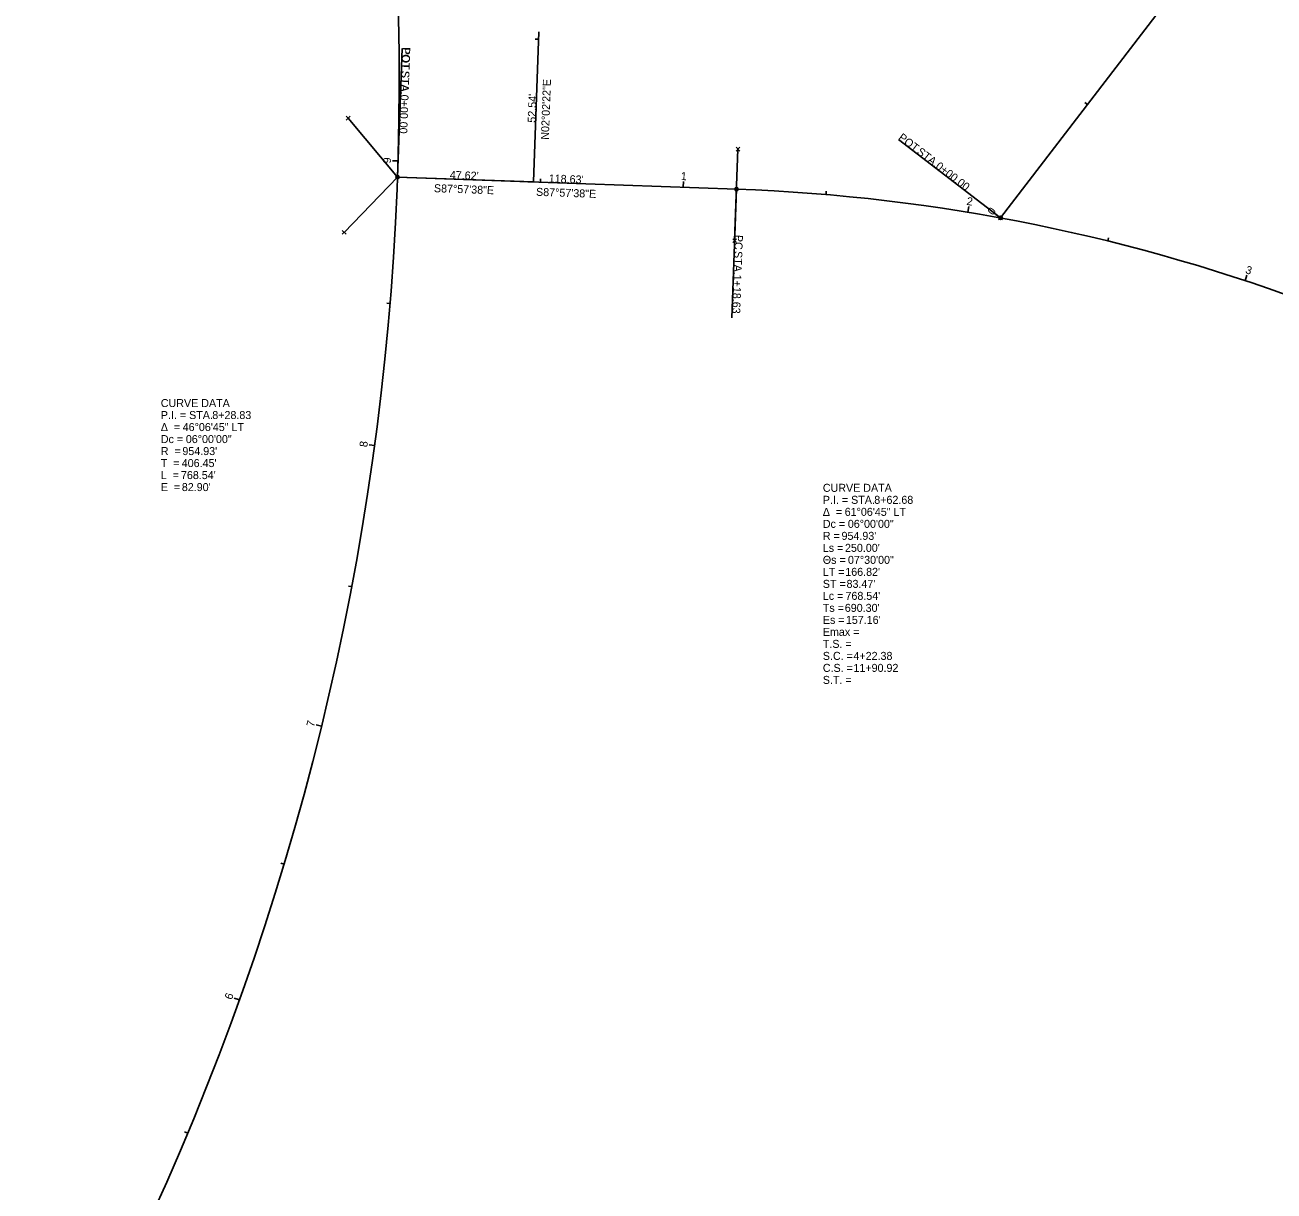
# Model space of a CAD drawing. Extents: x 1609531 to 1610891, y 471231 to 473177.
# Drawn here: x 1609986.3 to 1610423.2, y 471882.7 to 472290.7 of the extents above; entities that cross this region are included whole.
import ezdxf

# ---------------------------------------------------------------- set-up
doc = ezdxf.new("R2010")
doc.units = 0
for name, color, linetype in [('BR_X_SV_Shot_Marker', 7, 'Continuous'), ('Default', 7, 'Continuous'), ('DR_X_Ditch', 7, 'Continuous'), ('PM_X_Stop_Line', 7, 'Continuous'), ('PV_X_COP', 7, 'Continuous'), ('PV_X_Driveway', 7, 'Continuous'), ('PV_X_EOP', 7, 'Continuous'), ('PV_X_Shoulder_Aggregate', 7, 'Continuous'), ('RD_X_Cells', 7, 'Continuous'), ('RD_X_GR_Lt', 7, 'Continuous'), ('RD_X_GR_Rt', 7, 'Continuous'), ('SV_P_Mon_Cells_Set', 7, 'Continuous'), ('SV_X_Control_Cells_Found', 7, 'Continuous'), ('UT_X_Misc_Cells', 7, 'Continuous'), ('UT_X_Telecom_Cells', 7, 'Continuous')]:
    doc.layers.add(name, color=color, linetype=linetype)

msp = doc.modelspace()

# ---------------------------------------------------------------- linework, layer by layer
at = {"layer": 'Default'}
msp.add_line((1610116.63, 472237.49), (1610235.18, 472233.27), dxfattribs=at)
for centre, radius, start, end in [((1609162.3, 472271.47), 954.93, 329.64417, 15.75667), ((1610212.53, 471597.05), 636.62, 50.22722, 87.96056)]:
    msp.add_arc(centre, radius, start, end, dxfattribs=at)
at = {"layer": 'DR_X_Ditch'}
for p, q in [((1610166, 472285.76), (1610164.8, 472285.8)), ((1610164.22, 472235.79), (1610162.23, 472235.86))]:
    msp.add_line(p, q, dxfattribs=at)
at = {"layer": 'PM_X_Stop_Line'}
msp.add_line((1610116.63, 472237.49), (1610118.23, 472282.46), dxfattribs=at)
msp.add_circle((1610116.63, 472237.49), 0.6, dxfattribs=at)
at = {"layer": 'PV_X_COP'}
for p, q in [((1610098.69, 472257.45), (1610100.02, 472258.78)), ((1610098.69, 472258.78), (1610100.02, 472257.45)), ((1610235.02, 472246.59), (1610236.35, 472247.92)), ((1610235.02, 472247.92), (1610236.35, 472246.59)), ((1610326.85, 472222.53), (1610328.18, 472223.87)), ((1610326.85, 472223.87), (1610328.18, 472222.53)), ((1610097.26, 472217.47), (1610098.6, 472218.81)), ((1610097.26, 472218.81), (1610098.6, 472217.47)), ((1610233.88, 472214.61), (1610235.21, 472215.94)), ((1610233.88, 472215.94), (1610235.21, 472214.61))]:
    msp.add_line(p, q, dxfattribs=at)
at = {"layer": 'PV_X_Shoulder_Aggregate'}
for p, q in [((1610357.95, 472262.87), (1610356.99, 472263.6)), ((1610116.82, 472243.16), (1610114.82, 472243.22)), ((1610166.6, 472235.71), (1610166.64, 472236.91)), ((1610216.57, 472233.93), (1610216.64, 472235.93)), ((1610266.49, 472231.38), (1610266.6, 472232.57)), ((1610316.1, 472225.19), (1610316.42, 472227.16)), ((1610327.51, 472223.2), (1610325.93, 472224.42)), ((1610365.06, 472215.13), (1610365.35, 472216.29)), ((1610413.08, 472201.25), (1610413.71, 472203.15)), ((1610114.03, 472193.25), (1610112.83, 472193.35)), ((1610108.63, 472143.55), (1610106.65, 472143.81)), ((1610100.64, 472094.19), (1610099.46, 472094.42)), ((1610090.07, 472045.33), (1610088.13, 472045.8)), ((1610076.96, 471997.08), (1610075.82, 471997.43)), ((1610061.35, 471949.59), (1610059.47, 471950.26)), ((1610043.27, 471902.98), (1610042.17, 471903.44))]:
    msp.add_line(p, q, dxfattribs=at)
at = {"layer": 'RD_X_Cells'}
for p, q in [((1610116.63, 472237.49), (1610099.35, 472258.11)), ((1610234.54, 472215.28), (1610235.68, 472247.26)), ((1610097.93, 472218.14), (1610116.63, 472237.49))]:
    msp.add_line(p, q, dxfattribs=at)
at = {"layer": 'RD_X_GR_Rt'}
for p, q in [((1610164.22, 472235.79), (1610166.09, 472288.3)), ((1610116.63, 472237.49), (1610164.22, 472235.79))]:
    msp.add_line(p, q, dxfattribs=at)
at = {"layer": 'SV_P_Mon_Cells_Set'}
msp.add_circle((1610140.43, 472236.64), 0.05, dxfattribs=at)
msp.add_circle((1610140.43, 472236.64), 0.05, dxfattribs=at)
at = {"layer": 'SV_X_Control_Cells_Found'}
for p, q in [((1610116.63, 472237.49), (1610118.23, 472282.46)), ((1610327.51, 472223.2), (1610291.81, 472250.59)), ((1610235.18, 472233.27), (1610233.58, 472188.29))]:
    msp.add_line(p, q, dxfattribs=at)
for centre in [(1610116.63, 472237.49), (1610235.18, 472233.27), (1610327.51, 472223.2)]:
    msp.add_circle(centre, 0.6, dxfattribs=at)
at = {"layer": 'UT_X_Misc_Cells'}
for p, q in [((1610327.51, 472223.2), (1610631.82, 472619.93)), ((1610116.63, 472237.49), (1610235.18, 472233.27))]:
    msp.add_line(p, q, dxfattribs=at)
for centre, radius, start, end in [((1609162.3, 472271.47), 954.93, 329.64417, 15.75667), ((1610212.53, 471597.05), 636.62, 50.22722, 87.96056)]:
    msp.add_arc(centre, radius, start, end, dxfattribs=at)

# ---------------------------------------------------------------- texts
at = {"layer": 'BR_X_SV_Shot_Marker'}
for s, p in [('CURVE DATA', (1610033.83, 472157.03)), ('P.I. = STA. ', (1610033.83, 472152.83)), ('8+28.83', (1610051.83, 472152.83)), ('Δ  = ', (1610033.83, 472148.63)), ('46°06\'45" LT', (1610041.48, 472148.63)), ('Dc = ', (1610033.83, 472144.43)), ('06°00\'00"', (1610042.58, 472144.43)), ('R  = ', (1610033.83, 472140.23)), ("954.93'", (1610041.37, 472140.23)), ('T  = ', (1610033.83, 472136.03)), ("406.45'", (1610041.15, 472136.03)), ('L  = ', (1610033.83, 472131.83)), ("768.54'", (1610040.87, 472131.83)), ('E  = ', (1610033.83, 472127.63)), ("82.90'", (1610041.18, 472127.63)), ('CURVE DATA', (1610265.38, 472127.37)), ('P.I. = STA. ', (1610265.38, 472123.17)), ('8+62.68', (1610283.37, 472123.17)), ('Δ  = ', (1610265.38, 472118.97)), ('61°06\'45" LT', (1610273.03, 472118.97)), ('Dc = ', (1610265.38, 472114.77)), ('06°00\'00"', (1610274.13, 472114.77)), ('R = ', (1610265.38, 472110.57)), ("954.93'", (1610271.92, 472110.57)), ('Ls = ', (1610265.38, 472106.37)), ("250.00'", (1610273.13, 472106.37)), ('Θs = ', (1610265.38, 472102.17)), ('LT = ', (1610265.38, 472097.97)), ("166.82'", (1610273.23, 472097.97)), ('07°30\'00"', (1610274.17, 472102.17)), ('ST = ', (1610265.38, 472093.77)), ("83.47'", (1610273.68, 472093.77)), ('Lc = ', (1610265.38, 472089.57)), ("768.54'", (1610273.3, 472089.57)), ('Ts = ', (1610265.38, 472085.37)), ("690.30'", (1610273.07, 472085.37)), ('Es = ', (1610265.38, 472081.17)), ("157.16'", (1610273.44, 472081.17)), ('Emax = ', (1610265.38, 472076.97)), ('T.S. = ', (1610265.38, 472072.77)), ('S.C. = ', (1610265.38, 472068.57)), ('4+22.38', (1610276.09, 472068.57)), ('C.S. = ', (1610265.38, 472064.37)), ('11+90.92', (1610276.09, 472064.37)), ('S.T. = ', (1610265.38, 472060.17))]:
    msp.add_text(s, height=2.8, dxfattribs=at).set_placement(p)
at = {"layer": 'PM_X_Stop_Line'}
for s, p in [('POT', (1610118.29, 472283.02)), (' STA. ', (1610118.04, 472275.82)), ('0+00.00', (1610117.7, 472266.38))]:
    msp.add_text(s, height=2.8, rotation=267.9606, dxfattribs=at).set_placement(p)
at = {"layer": 'PV_X_Driveway'}
for s, rotation, p in [("52.54'", 87.9606, (1610164.92, 472256.49)), ("47.62'", 357.9606, (1610134.87, 472236.88))]:
    msp.add_text(s, height=2.8, rotation=rotation, dxfattribs=at).set_placement(p)
at = {"layer": 'PV_X_EOP'}
msp.add_text("118.63'", height=2.8, rotation=357.9606, dxfattribs=at).set_placement((1610169.48, 472235.64))
at = {"layer": 'PV_X_Shoulder_Aggregate'}
for s, rotation, p in [('9', 88.3014, (1610114.29, 472242.25)), ('1', 357.9606, (1610215.67, 472236.46)), ('2', 350.6373, (1610315.54, 472227.81)), ('0', 52.5106, (1610324.9, 472223.9)), ('3', 341.6373, (1610412.96, 472203.93)), ('8', 82.3014, (1610106.01, 472142.87)), ('7', 76.3014, (1610087.4, 472044.94)), ('6', 70.3014, (1610058.65, 471949.47))]:
    msp.add_text(s, height=2.8, rotation=rotation, dxfattribs=at).set_placement(p)
at = {"layer": 'RD_X_GR_Lt'}
for s, rotation, p in [('N02°02\'22"E', 87.9606, (1610169.55, 472250.52)), ('S87°57\'38"E', 357.9606, (1610129.32, 472232.23))]:
    msp.add_text(s, height=2.8, rotation=rotation, dxfattribs=at).set_placement(p)
at = {"layer": 'SV_X_Control_Cells_Found'}
for s, rotation, p in [('POT', 267.9606, (1610118.28, 472282.82)), (' STA. ', 267.9606, (1610118.03, 472275.7)), ('0+00.00', 267.9606, (1610117.7, 472266.38)), ('POT', 322.5106, (1610291.54, 472250.84)), (' STA. ', 322.5106, (1610297.2, 472246.5)), ('0+00.00', 322.5106, (1610304.59, 472240.82)), ('PC', 267.9606, (1610234.65, 472217.31)), (' STA. ', 267.9606, (1610234.49, 472212.71)), ('1+18.63', 267.9606, (1610234.16, 472203.39))]:
    msp.add_text(s, height=2.8, rotation=rotation, dxfattribs=at).set_placement(p)
at = {"layer": 'UT_X_Telecom_Cells'}
msp.add_text('S87°57\'38"E', height=2.8, rotation=357.9606, dxfattribs=at).set_placement((1610165.03, 472230.96))

doc.saveas('drawing.dxf')
